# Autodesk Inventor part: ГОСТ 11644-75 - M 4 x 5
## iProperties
Created: 2006-04
Part Number: ГОСТ 11644-75 - M 4 x 5
Material: Сталь низкоуглеродистая
Description: Болт
Vendor: Autodesk Inc.
Document SubType Name: Modeling
Standard: ГОСТ 11644-75
Designer: Калинин
Standards Organization: GOST
Language: ru-RU
Size Designation: M 4 x 5
Categories: <MemberInstance Version="R10.0.0"><Categories><Category DisplayName="Крепежные изделия" InternalName="e4da775c-781d-43d5-af7c-5136215cf5a6" Mnemonic="FSTN"><Cat
Author: Калинин
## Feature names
1. Базовый элемент [Revolution]
2. Сопряжение1 [Fillet]
3. Прорезь [Extrusion]
4. Фаска1 [Chamfer]
